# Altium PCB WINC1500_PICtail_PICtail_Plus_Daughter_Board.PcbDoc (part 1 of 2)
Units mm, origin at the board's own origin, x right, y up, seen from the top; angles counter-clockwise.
Board outline 40 x 55.01 mm, 2 copper layers (Top Layer, Bottom Layer), stack 1.571 mm thick; 57 components, 48 nets, 242 pads, 214 vias.
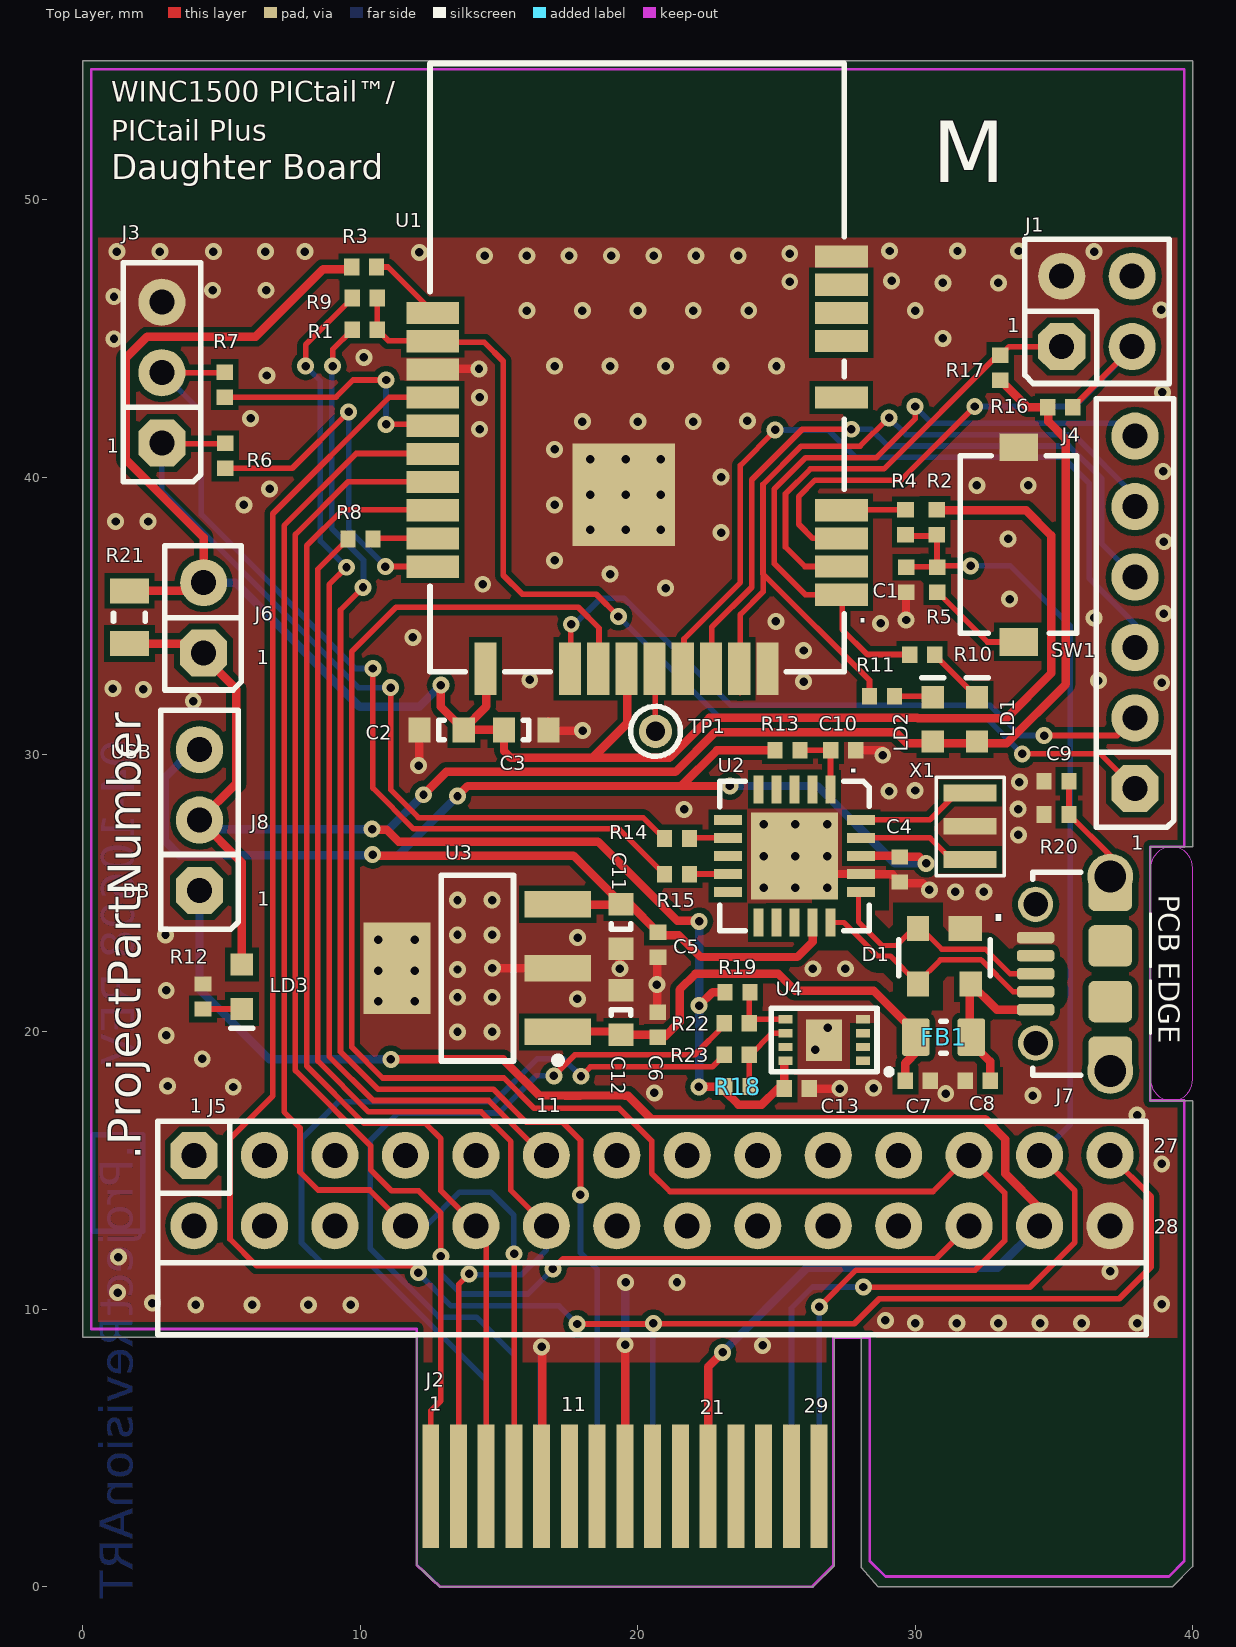
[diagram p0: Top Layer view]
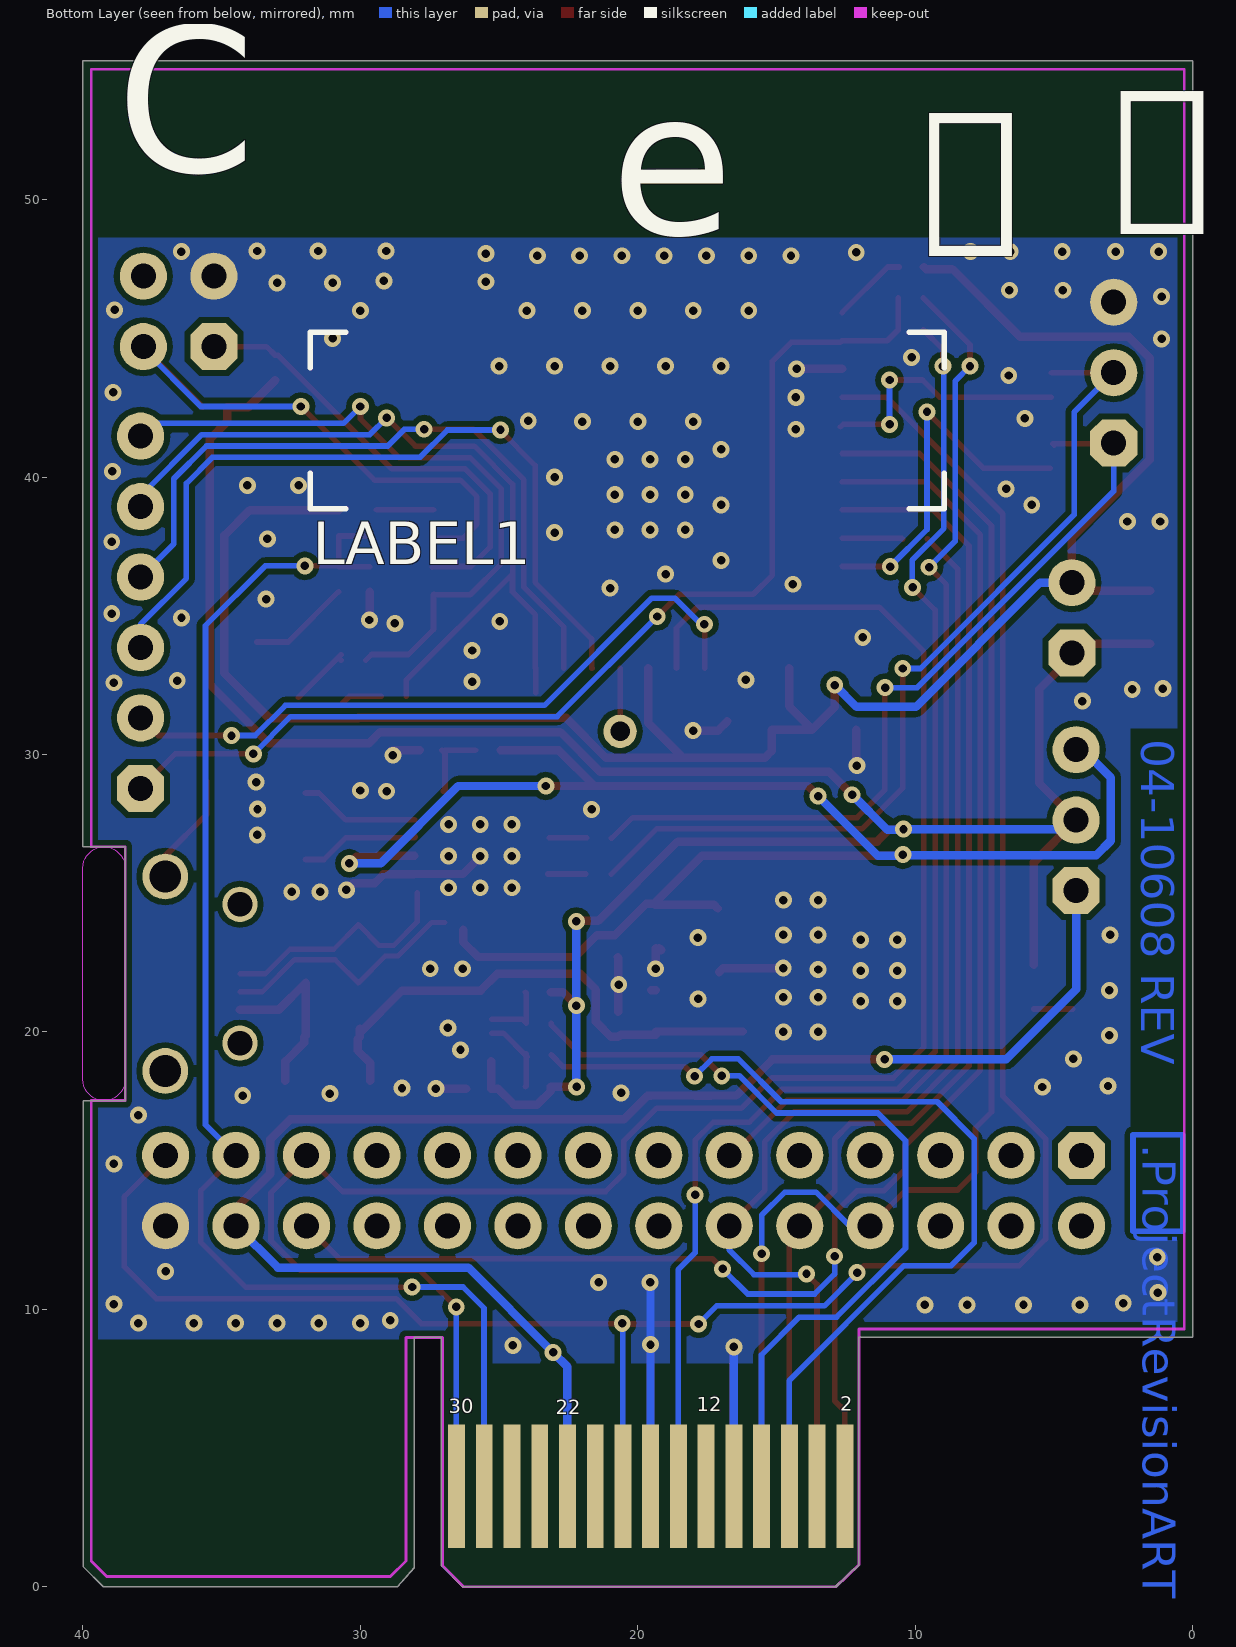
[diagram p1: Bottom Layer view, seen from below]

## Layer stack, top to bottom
Top Solder: solder mask 0.0102, Solder Resist, Dk 3.5
Top Layer: signal copper 0.0356
Dielectric1: core 1.5, FR-4, Dk 4.6
Bottom Layer: signal copper 0.0356
Bottom Solder: solder mask 0.0102, Solder Resist, Dk 3.5

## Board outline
12.862,0 26.317,0 26.317,-0.01 27.078,0.751 27.078,8.989 28.06,8.989 28.06,0.683 28.662,0 39.271,0 39.997,0.726 39.997,17.526 38.475,17.526 38.475,26.675 40,26.675 40,55 0,55 0,8.989 12.029,8.989 12.029,0.79

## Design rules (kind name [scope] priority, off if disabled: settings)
Clearance Clearance_U4 [(InComponent('U4') AND IsPad)] p1: gap=0.2
Clearance "Polygon - USB trace" [InPolygon vs (InNet('USB_P') OR InNet('USB_N'))] p2: gap=0.508
Clearance Clearance_usb [(InNet('USB_N') OR InNet('USB_P'))] p3: gap=0.178
Clearance GND_Via [(IsVia AND InNet('GND')) vs (OnLayer('Keep-Out Layer'))] p4: gap=0.127
Clearance J2 [InComponent('J2') vs (OnLayer('Keep-Out Layer'))] p5: gap=0.1
Clearance [All] p6: gap=0.203
ComponentClearance [All] p1: gap=0.2 collisioncheckmode=3 verticalgap=0.2 showdistances=FALSE
DiffPairsRouting [All] p1: maxlimit=0.191 minlimit=0.191 mostfreqgap=0.191 toplayer_minwidth=0.191 toplayer_maxwidth=0.191 toplayer_prefwidth=0.191 bottomlayer_minwidth=0.191 bottomlayer_maxwidth=0.191 bottomlayer_prefwidth=0.191 maxuncoupledlength=12.7
FabricationTestPointUsage TestPointUsage [All] p1: valid=0 allowmultiple=FALSE
FabricationTestpoint Testpoint [All] p1: side=3 testpointundercomponent=TRUE minsize=1.016 maxsize=2.54 preferedsize=1.524 minholesize=0 maxholesize=1.016 preferedholesize=0.813 testpointgrid=0.025 allowsidetop=TRUE allowsidebottom=TRUE usegrid=TRUE gridtolerance=0
HoleSize [All] p1: absolutevalues=TRUE maxlimit=5 minlimit=0.3 maxpercent=80.000 minpercent=20.000
HoleToHoleClearance [All] p1: gap=0.3 allowstackedmicrovias=TRUE
MinimumSolderMaskSliver MinimumSolderMaskSliver_U2_14_18 [(InComponent('U2') AND IsPad)] p1: minsoldermaskwidth=0.099
MinimumSolderMaskSliver MinimumSolderMaskSliver_U1 [(InComponent('U1') AND IsPad)] p2: minsoldermaskwidth=0.015
MinimumSolderMaskSliver MinimumSolderMaskSliver_U4 [(InComponent('U4') AND IsPad)] p3: minsoldermaskwidth=0.046
MinimumSolderMaskSliver MinimumSolderMaskSliver_J7 [(InComponent('J7') AND IsPad)] p4: minsoldermaskwidth=0.089
MinimumSolderMaskSliver [All] p5: minsoldermaskwidth=0.1
PlaneClearance [All] p1: clearance=0.5
PlaneConnect PlaneConnect_full [IsVia] p1: planeconnectstyle=Direct reliefexpansion=0.5 reliefentries=4 reliefconductorwidth=0.3 reliefairgap=0.3
PlaneConnect [All] p2: planeconnectstyle=Direct reliefexpansion=0.3 reliefentries=4 reliefconductorwidth=0.25 reliefairgap=0.25
PolygonConnect [All] p1: connectstyle=Direct reliefconductorwidth=0.3 reliefentries=4 polygonreliefangle="90 Angle" airgapwidth=0.25
RoutingVias [All] p1: holewidth=0.305 width=0.61 viastyle="Through Hole" minholewidth=0.305 minwidth=0.61 maxholewidth=1.6 maxwidth=2.5
ShortCircuit [IsNet] p1: allowed=FALSE
SilkToSilkClearance [All] p1: silktosilkclearance=0.1
SilkToSolderMaskClearance SilkscreenOverComponentPads [IsPad] p1: minsilkscreentomaskgap=0.1 clearancetoexposedcopper=TRUE
SolderMaskExpansion SolderMaskExpansionTenting [IsVia] p1: expansion=-0.3
SolderMaskExpansion [All] p2: expansion=0.1
Width Width_Vcc_GND [(InNet('VCC_USB_5V0') OR InNet('VCC_USB_3V3') OR InNet('VCC_TARGET_3V3') OR InNet('VCC_MODULE_3V3') OR InNet('VCC_BASE_BOARD_3V3')OR InNet('GND')OR InNet('NetC8_2'))] p1: maxlimit=0.305 minlimit=0.305 preferedwidth=0.305
Width [All] p2: maxlimit=0.203 minlimit=0.2 preferedwidth=0.203
17 further rules are at their usual default settings.

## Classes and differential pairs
differential pair USB: +USB_P -USB_N

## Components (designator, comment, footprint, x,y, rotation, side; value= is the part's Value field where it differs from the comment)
C1 "Capacitor NP" CAP_C_0402 29.675,36.3 r90 top
C2 "Capacitor NP" CAP_C_0603 12.929,30.886 r0 top
C3 "Capacitor NP" CAP_C_0603 15.977,30.886 r180 top
C4 "Capacitor NP" CAP_C_0402 29.439,25.857 r90 top
C5 "Capacitor NP" CAP_C_0402 20.726,23.139 r90 top
C6 "Capacitor NP" CAP_C_0402 20.716,20.259 r90 top
C7 "Capacitor NP" CAP_C_0402 30.092,18.237 r0 top
C8 "Capacitor NP" CAP_C_0402 32.251,18.237 r0 top
C9 "Capacitor NP" CAP_C_0402 35.096,29.032 r0 top
C10 "Capacitor NP" CAP_C_0402 27.407,30.15 r180 top
C11 "Capacitor NP" CAP_C_0603 19.4,23.8 r90 top
C12 "Capacitor NP" CAP_C_0603 19.4,20.7 r270 top
C13 "Capacitor NP" CAP_C_0402 25.73,17.958 r180 top
D1 "PRTR5V0U2X" SOT-143 31.05,22.725 r180 top
FB1 "Ferrite Bead" IND_C_0805 31.023,19.812 r180 top
J1 "Header 2x2" HDR_M_2.54_2x2 36.551,45.974 r0 top locked
J2 "PICtail plus connector" CON_EDGE-CARD_PCB_RA_PICTAIL_PLUS_30A_Alternate1 12.535,0 r0 top locked
J3 "Header 1x3" HDR_M_2.54_1x3 2.845,43.764 r90 top locked
J4 "Header 1x6" HDR_M_2.54_1x6 37.922,35.128 r90 top locked
J5 "Header 2x14" HDR_M_2.54_2x14_RA 4.003,15.55 r0 top locked
J6 "Header 1x2" HDR_M_2.54_1x2 4.35,34.925 r90 top locked
J7 "CON USB2.0 Mini_Micro" CON_USB_Micro-AB_SMD_TH_RA_FCI_10118194-0001LF 37.033,22.098 r270 top locked
J8 "Header 1x3" HDR_M_2.54_1x3 4.2,27.635 r90 top locked
LABEL1 "LABEL_08-00028" LABEL_08-00028 20.376,42.04 r0 bottom
LD1 "LED" LED_0603_RED 32.233,31.264 r90 top
LD2 "LED" LED_0603_Orange 30.632,31.264 r90 top
LD3 "LED" LED_0603_GREEN 5.725,21.625 r270 top
R1 "Resistor" RES_C_0402 10.16,45.314 r0 top
R2 "Resistor" RES_C_0402 30.775,38.375 r90 top
R3 "Resistor" RES_C_0402 10.135,47.574 r180 top
R4 "Resistor" RES_C_0402 29.65,38.375 r270 top
R5 "Resistor" RES_C_0402 30.8,36.3 r90 top
R6 "Resistor" RES_C_0402 5.131,40.767 r270 top
R7 "Resistor" RES_C_0402 5.105,43.332 r270 top
R8 "Resistor" RES_C_0402 10.008,37.77 r0 top
R9 "Resistor" RES_C_0402 10.16,46.457 r180 top
R10 "Resistor" RES_C_0402 30.251,33.601 r0 top
R11 "Resistor" RES_C_0402 28.8,32.1 r0 top
R12 "Resistor" RES_C_0402 4.325,21.275 r270 top
R13 "Resistor" RES_C_0402 25.4,30.15 r180 top
R14 "Resistor" RES_C_0402 21.412,26.975 r0 top
R15 "Resistor" RES_C_0402 21.412,25.679 r0 top
R16 "Resistor" RES_C_0402 35.23,42.52 r180 top
R17 "Resistor" RES_C_0402 33.071,43.942 r270 top
R18 "Resistor" RES_C_0402 23.596,18.032 r180 top
R19 "Resistor" RES_C_0402 23.596,21.436 r180 top
R20 "Resistor" RES_C_0402 35.096,27.838 r0 top
R21 "Resistor" RES_C_0805 1.675,34.95 r270 top
R22 "Resistor" RES_C_0402 23.571,20.318 r180 top
R23 "Resistor" RES_C_0402 23.571,19.175 r180 top
SW1 "Switch 2 Pin" SW_TACT_SMD_CK_KSR231GLFS 33.731,37.567 r180 top
TP1 "Test Point No BOM" TP_1.2x0.7 20.637,30.836 r0 top
U1 "MODULE ATWINC1510-MR210PB" MOD_ATWINC1500-MR210PB 19.975,43.95 r0 top locked
U2 "MCP2200 QFN-20" QFN-20_5X5 25.649,26.343 r270 top
U3 "MCP182XS SOT-223-3_DDPAK-3_TO-220-3" SOT-223-3 14.22,22.301 r90 top
U4 "ATECC508A UDFN-8" UDFN-8_2X3_EP1.5X1.3 26.719,19.706 r180 top
X1 "CSTCE12M0G15L99-R0" RESONATOR_CSTCE-G_L3.2W1.3H0.8 31.979,27.413 r90 top

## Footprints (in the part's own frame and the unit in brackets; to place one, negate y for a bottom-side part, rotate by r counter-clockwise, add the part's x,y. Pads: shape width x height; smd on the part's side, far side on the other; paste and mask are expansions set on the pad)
CAP_C_0402 [mm] "Chip Capacitor, 2-Leads, Body 1.0x0.5mm, IPC High Density"
  rect 0.55x0.6 smd: 1(-0.45,0) 2(0.45,0)
  body extent -0.5,-0.3 0.5,0.3, height 0.2
CAP_C_0603 [mm] "Chip Capacitor, 2-Leads, Body 1.6x0.8mm, IPC Medium Density"
  rect 0.8x0.9 smd: 1(-0.8,0) 2(0.8,0)
  silkscreen extent -0.1,-0.35 0.1,0.35, body extent -0.8,-0.4 0.8,0.4, height 0.3
CON_EDGE-CARD_PCB_RA_PICTAIL_PLUS_30A_Alternate1 [mm] "Mini Edge Mating Card for Samtec MEC1-160-2-X-D"
  rect 0.61x4.45 smd paste-1: 1(0,3.615) 3(1,3.615) 5(2,3.615) 7(3,3.615) 9(4,3.615) 11(5,3.615) 13(6,3.615) 15(7,3.615) 17(8,3.615) 19(9,3.615) 21(10,3.615) 23(11,3.615) 25(12,3.615) 27(13,3.615) 29(14,3.615)
  rect 0.61x4.45 smd far side paste-1: 2(0,3.615) 4(1,3.615) 6(2,3.615) 8(3,3.615) 10(4,3.615) 12(5,3.615) 14(6,3.615) 16(7,3.615) 18(8,3.615) 20(9,3.615) 22(10,3.615) 24(11,3.615) 26(12,3.615) 28(13,3.615) 30(14,3.615)
  body extent -0.1,1.8 0.4,2.3
CON_USB_Micro-AB_SMD_TH_RA_FCI_10118194-0001LF [mil] "FCI USB Micro-AB SMD RA L5W8.8H2.8"
  round 65 hole 45: 0(-138,0) 0(138,0)
  rrect30% 59x62 smd paste-2: 0(-118.5,0) 0(-39.5,0) 0(39.5,0) 0(118.5,0)
  round 50 hole 35: 0(-98.5,-106)
  rrect100% 50x50 hole 35: 0(98.5,-106)
  rrect50% 16x53 smd paste-1.8 mask+3: 1(51.18,-106) 2(25.59,-106) 3(0,-106) 4(-25.59,-106) 5(-51.18,-106)
  Keep-Out Layer board cut-out: 150,57 161.48,59.28 171.21,65.79 177.72,75.52 180,87 180,87 177.72,98.48 171.21,108.21 161.48,114.72 150,117 150,117 -150,117 -161.48,114.72 -171.21,108.21 -177.72,98.48 -180,87 -180,87 -177.72,75.52 -171.21,65.79 -161.48,59.28 -150,57 -150,57
  Keep-Out Layer board cut-out: 150,57 161.48,59.28 171.21,65.79 177.72,75.52 180,87 180,87 177.72,98.48 171.21,108.21 161.48,114.72 150,117 150,117 -150,117 -161.48,114.72 -171.21,108.21 -177.72,98.48 -180,87 -180,87 -177.72,75.52 -171.21,65.79 -161.48,59.28 -150,57 -150,57
  silkscreen extent -144,-110 144,57, body extent -158,-114 158,106, height 108
HDR_M_2.54_1x2 [mm] "Header Male Vertical 4 Way 2.54mm Pitch"
  oct 1.7x1.7 hole 0.9: 1(-1.27,0)
  round 1.7 hole 0.9: 2(1.27,0)
  silkscreen extent -2.6,-1.35 2.6,1.4, body extent -2.54,-1.27 2.54,1.27, height 5.94
HDR_M_2.54_1x3 [mm] "Header Male Vertical 4 Way P=2.54mm"
  oct 1.7x1.7 hole 0.9: 1(-2.54,0)
  round 1.7 hole 0.9: 2(0,0) 3(2.54,0)
  silkscreen extent -3.94,-1.4 3.96,1.4, body extent -3.8,-1.26 3.82,1.28, height 5.94
HDR_M_2.54_1x6 [mm] "Header Male Vertical 6 Way 2.54mm Pitch"
  oct 1.7x1.7 hole 0.9: 1(-6.35,0)
  round 1.7 hole 0.9: 2(-3.81,0) 3(-1.27,0) 4(1.27,0) 5(3.81,0) 6(6.35,0)
  silkscreen extent -7.75,-1.4 7.7,1.4, body extent -7.62,-1.27 7.62,1.27, height 8.38
HDR_M_2.54_2x2 [mm] "Header Male Vertical 2x2 Way 2.54mm Pitch"
  oct 1.7x1.7 hole 0.9: 1(-1.27,-1.27)
  round 1.7 hole 0.9: 2(-1.27,1.27) 3(1.27,-1.27) 4(1.27,1.27)
  silkscreen extent -2.6,-2.6 2.6,2.6, body extent -2.54,-2.54 2.54,2.54, height 5.94
HDR_M_2.54_2x14_RA [mm] "Header Male R/A 2x14 Way 2.54mm Pitch"
  oct 1.7x1.7 hole 0.9: 1(0,0)
  round 1.7 hole 0.9: 2(0,-2.54) 3(2.54,0) 4(2.54,-2.54) 5(5.08,0) 6(5.08,-2.54) 7(7.62,0) 8(7.62,-2.54) 9(10.16,0) 10(10.16,-2.54) 11(12.7,0) 12(12.7,-2.54) 13(15.24,0) 14(15.24,-2.54) 15(17.78,0) 16(17.78,-2.54) 17(20.32,0) 18(20.32,-2.54) 19(22.86,0) 20(22.86,-2.54) 21(25.4,0) 22(25.4,-2.54) 23(27.94,0) 24(27.94,-2.54) 25(30.48,0) 26(30.48,-2.54) 27(33.02,0) 28(33.02,-2.54)
  silkscreen extent -1.3,-6.47 34.32,1.23, body extent -1.27,-12.56 34.29,0.32, height 5.04
IND_C_0805 [mm] "Chip Inductor, 2-Leads, Body 2.0x1.3mm, IPC Medium Density"
  rrect20% 1x1.35 smd: 1(-1,0) 2(1,0)
  silkscreen extent -0.1,-0.58 0.1,0.58, body extent -1,-0.6 1,0.6, height 0.95
LABEL_08-00028 [mm] "Small Serial Number Assembly Label"
  silkscreen extent -11.43,-3.17 11.43,3.17, body extent -11.43,-3.17 11.43,3.17, height 0.3
LED_0603_GREEN [mm] "LED chip 0603"
  rect 0.8x0.8 smd: 1(-0.8,0) 2(0.8,0)
  silkscreen extent 1.5,-0.4 1.5,0.4, body extent -0.81,-0.4 0.81,0.4, height 0.6
LED_0603_Orange [mm] "LED chip 0603"
  rect 0.8x0.8 smd: 1(-0.8,0) 2(0.8,0)
  silkscreen extent 1.5,-0.4 1.5,0.4, body extent -0.81,-0.4 0.81,0.4, height 0.6
LED_0603_RED [mm] "LED chip 0603"
  rect 0.8x0.8 smd: 1(-0.8,0) 2(0.8,0)
  silkscreen extent 1.5,-0.4 1.5,0.4, body extent -0.81,-0.4 0.81,0.4, height 0.6
MOD_ATWINC1500-MR210PB [mm]
  rect 1.9x0.8 smd: 1(7.365,-8.19) 2(7.365,-7.174) 3(7.365,-6.158) 4(7.365,-5.142) 5(7.365,-1.078) 6(7.365,0.954) 7(7.365,1.97) 8(7.365,2.986) 9(7.365,4.002) 10(-7.365,1.964) 11(-7.365,0.948) 12(-7.365,-0.068) 13(-7.365,-1.084) 14(-7.365,-2.1) 15(-7.365,-3.116) 16(-7.365,-4.132) 17(-7.365,-5.148) 18(-7.365,-6.164) 19(-7.365,-7.18)
  rect 0.8x1.9 smd: 20(-5.465,-10.86) 21(-2.417,-10.86) 22(-1.401,-10.86) 23(-0.385,-10.86) 24(0.631,-10.86) 25(1.647,-10.86) 26(2.663,-10.86) 27(3.679,-10.86) 28(4.695,-10.86)
  rect 3.7x3.7 smd: 29(-0.485,-4.59)
  silkscreen extent -7.46,-10.96 7.46,10.96, body extent -7.36,-10.86 7.37,10.86, height 2.11
QFN-20_5X5 [mm]
  rect 1x0.35 smd: 1(-2.4,1.3) 2(-2.4,0.65) 3(-2.4,0) 4(-2.4,-0.65) 5(-2.4,-1.3) 11(2.4,-1.3) 12(2.4,-0.65) 13(2.4,0) 14(2.4,0.65) 15(2.4,1.3)
  rect 0.35x1 smd: 6(-1.3,-2.4) 7(-0.65,-2.4) 8(0,-2.4) 9(0.65,-2.4) 10(1.3,-2.4) 16(1.3,2.4) 17(0.65,2.4) 18(0,2.4) 19(-0.65,2.4) 20(-1.3,2.4)
  rect 3.15x3.15 smd paste+0: 21(0,0)
  silkscreen extent -2.7,-2.7 2.7,2.7, body extent -2.51,-2.51 2.51,2.51, height 0.89
RES_C_0402 [mm] "Chip Resistor, 2-Leads, Body 1.0x0.5mm, IPC Medium Density"
  rect 0.55x0.6 smd: 1(-0.45,0) 2(0.45,0)
  body extent -0.5,-0.3 0.5,0.3, height 0.2
RES_C_0805 [mm] "Chip Resistor, 2-Leads, Body 2.0x1.3mm, IPC Medium Density"
  rect 0.9x1.4 smd: 1(-0.95,0) 2(0.95,0)
  silkscreen extent -0.15,-0.58 0.15,0.58, body extent -1,-0.63 1,0.63, height 0.78
RESONATOR_CSTCE-G_L3.2W1.3H0.8 [mm] "Resonator Murata CSTCE G 8-13.99 MHz L=3.2mm W=1.3mm H=0.8mm"
  rect 0.6x1.9 smd: 1(-1.2,0) 2(0,0) 3(1.2,0)
  silkscreen extent -1.78,-1.22 1.78,1.23, body extent -1.6,-0.65 1.6,0.65, height 0.7
SOT-143 [mm] "SOT143, 4-Leads, Body 2.9x2.5mm (max), Pitch 1.90mm, IPC Medium Density"
  rect 1.2x0.9 smd: 1(-0.75,-1)
  rect 0.8x0.9 smd: 2(0.95,-1) 3(0.95,1) 4(-0.95,1)
  silkscreen extent -1.65,-0.6 1.65,0.7, body extent -1.46,-1.21 1.46,1.21, height 1
SOT-223-3 [mm] "SOT223-3, 4-Leads, Body 6.7x7.3mm (max), Pitch 2.30mm, IPC Medium Density"
  rect 0.95x2.4 smd: 1(-2.3,-2.9) 2(0,-2.9) 3(2.3,-2.9)
  rect 3.3x2.4 smd: 2(0,2.9)
  silkscreen extent -3.45,-3.03 3.35,1.3, body extent -3.3,-3.55 3.4,3.65, height 1.85
SW_TACT_SMD_CK_KSR231GLFS [mm]
  rect 1.4x1 smd: 1(0,-3.51) 2(0,3.51)
  silkscreen extent -2.1,-3.2 2.1,3.2, body extent -1.91,-3.8 1.92,3.81, height 4.5
TP_1.2x0.7 [mm] "Test Point round, diam=1.2mm, drill=0.7mm"
  round 1.2 hole 0.7: 1(0,0)
  silkscreen extent -0.9,-0.9 0.9,0.9
UDFN-8_2X3_EP1.5X1.3 [mm] "PQFN, 8-Leads, Body 3.00x2.00mm, Pitch 0.50mm, Thermal Pad 1.30x1.50mm, IPC Medium Density"
  rect 0.5x0.3 smd paste-0.046 mask+0.076: 1(-1.398,0.75) 2(-1.398,0.25) 3(-1.398,-0.25) 4(-1.398,-0.75) 5(1.398,-0.75) 6(1.398,-0.25) 7(1.398,0.25) 8(1.398,0.75)
  rect 1.3x1.5 smd paste-0.076: 9(0,0)
  silkscreen extent -2.44,-1.14 1.91,1.24, body extent -1.55,-1.05 1.55,1.05, height 0.64

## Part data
C1 C4 C10 C13: library part CAP0279, "Capacitor"
C2: library part CAP0542, "Capacitor"
C3 C11 C12: library part CAP0602, "Capacitor"
C5 C6: library part CAP1207, "Capacitor"
C7 C8: library part CAP0566, "Capacitor"
C9: library part CAP1479, "Capacitor"
D1: library part DIODE1279
FB1: library part IND1291
J1: library part CON0057
J2: library part CON1387
J3 J8: library part CON0465
J4: library part CON0438
J5: library part CON0174
J6: library part CON1108
J7: library part CON1383, "Connector USB Mini"
LD1: library part DIODE1058
LD2: library part LED0123
LD3: library part LED0113
R1 R4 R6 R7 R8 R9 R14 R15 R22 R23: library part RSMT0730
R2: library part RES1012
R3 R20: library part RES1019
R5: library part RES1385
R10 R11 R12: library part RSMT0731
R13 R16 R17 R18 R19: library part RES1462
R21: library part RSMT0519
SW1: library part SWITCH1023, "Switch"
TP1: library part CON1128, "Test Point"
U1: library part MIC6777
U2: library part MIC6326, "USB 2.0 to UART Protocol Conv with GPIO QFN20"
U3: library part MIC0763, "LDO"
U4: library part IC1305
X1: library part OSC1027, "Resonator"

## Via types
v1: diameter 0.61, hole 0.305, Top Layer to Bottom Layer, 214 vias

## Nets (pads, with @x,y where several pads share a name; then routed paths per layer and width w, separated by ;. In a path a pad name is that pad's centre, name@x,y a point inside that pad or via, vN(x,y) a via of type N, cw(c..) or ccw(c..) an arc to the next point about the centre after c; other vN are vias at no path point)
CHIP_EN: J2.30 J5.23 U1.22 | length 69
  Top Layer w0.203: U1.22@18.603,33.103 18.603,34.558 17.855,35.306 14.381,35.306 14.378,35.309 11.286,35.309 9.688,33.71 9.688,19.452 10.801,18.339 15.171,18.339 16.263,17.247 19.328,17.247 20.5,16.075 20.5,14.908 21.158,14.249 30.642,14.249 J5.23@31.943,15.55 31.943,15.482 33.223,14.202 33.223,12.473 32.165,11.415 27.869,11.415 v1(26.543,10.089)
  Bottom Layer w0.203: J2.30@26.542,3.603 v1(26.543,10.089) v1(26.543,10.089)
ECC_I2C_SCL: J2.6 R23.2 | length 33.3
  Top Layer w0.203: v1(17.953,18.402) 18.291,18.74 22.686,18.74 R23.2@23.121,19.175
  Bottom Layer w0.203: J2.6@14.542,3.603 14.542,7.435 10.402,11.575 8.7,11.575 7.875,12.4 7.875,16.15 9.206,17.481 14.827,17.481 16.373,19.027 17.328,19.027 v1(17.953,18.402)
ECC_I2C_SDA: J2.8 R22.2 | length 30
  Top Layer w0.203: v1(16.972,18.418) 17.73,19.175 22.052,19.175 23.121,20.243 R22.2@23.121,20.318
  Bottom Layer w0.203: J2.8@15.542,3.603 15.542,8.358 14.181,9.719 12.833,9.719 10.35,12.202 10.35,16.075 11.35,17.075 14.996,17.075 16.338,18.418 v1(16.972,18.418)
GND: C1.1 C2.1 C3.1 C4.1 C5.1 C6.2 C7.2 C8.1 C9.1 C10.1 C11.1 C12.1 C13.1 D1.1 J1.2 J2.9 J2.10 J2.15 J2.16 J3.3 J5.28 J7.5 R12.1 R20.1 SW1.1 U1.9 U1.12 U1.28 U1.29 U2.17 U2.21 U3.2 U4.4 U4.9 X1.2 | length 41
  Top Layer w0.305: v1(12.1,29.6) 12.129,29.629 C2.1@12.129,30.886 ; U1.12@12.634,43.898 14.273,43.898 v1(14.275,43.9) ; v1@14.707,22.352 v1(14.757,22.301) 16.921,22.301 U3.2@17.073,22.149 ; v1@16.523,8.496 16.561,8.458 16.561,3.622 J2.9@16.542,3.603 ; v1@16.535,8.509 v1(16.535,8.648) ; C3.1@16.777,31.191 17.107,30.861 v1(18.009,30.861) ; C11.1@19.152,22.949 C11.1@19.228,23.025 ; C12.1@19.355,21.501 C12.1@19.52,21.501 ; v1(19.355,22.276) C11.1@19.355,23.025 ; J2.15@19.542,3.603 v1(19.542,8.728) ; C6.2@20.701,20.719 20.701,21.717 20.706,21.722 20.706,22.669 C5.1@20.726,22.689 ; U2.21@25.648,26.343 26.298,25.693 U2.17@28.049,25.693 28.065,25.677 29.169,25.677 C4.1@29.439,25.407 ; C13.1@26.18,17.958 v1(27.28,17.958) ; C10.1@27.857,30.15 28.829,30.15 v1(28.829,29.972) ; C4.1@29.484,25.362 30.269,25.362 v1(30.508,25.123) ; C1.1@29.667,35.872 29.667,34.856 v1(29.675,34.849)
  Bottom Layer w0.305: v1(16.535,8.648) 16.542,8.655 J2.10@16.542,3.603 ; J2.16@19.542,3.603 v1(19.542,8.728) 19.542,10.957 v1(19.558,10.973)
  other v1: 24.501,8.702 30,9.5 31.5,9.5 33,9.5 34.5,9.5 36,9.5 38,9.5 28.925,9.6 4.064,10.16 6.096,10.16 8.128,10.16 9.652,10.16 38.887,10.185 2.5,10.225 1.25,10.6 21.412,10.973 37.023,11.369 1.275,11.885 38.887,15.24 38,17 34.239,17.704 31.1,17.775 20.6,17.8 28.5,17.975 5.415,18.014 3.05,18.05 4.3,19.025 26.391,19.355 3,19.875 13.5,20 14.75,20 26.848,20.142 10.643,21.107 11.963,21.107 17.823,21.191 13.5,21.25 14.75,21.25 3,21.5 20.686,21.707 10.643,22.212 11.963,22.212 13.5,22.25 26.314,22.276 27.483,22.276 10.643,23.317 11.963,23.317 17.831,23.398 2.975,23.5 13.5,23.5 14.75,23.5 13.5,24.75 14.75,24.75 31.45,25.05 32.475,25.05 24.536,25.197 25.679,25.197 26.822,25.197 24.536,26.34 25.679,26.34 26.822,26.34 33.718,27.099 24.536,27.483 25.679,27.483 26.822,27.483 21.666,28.024 33.708,28.034 29.058,28.677 29.997,28.702 33.757,29.007 3.975,31.925 2.175,32.35 1.075,32.375 38.887,32.588 25.975,32.625 36.601,32.664 16.104,32.69 25.975,33.75 11.89,34.219 28.755,34.729 24.975,34.8 36.449,34.925 38.964,35.077 33.4,35.6 21,36 14.409,36.137 19,36.5 17,37 38.964,37.668 33.35,37.775 23,38 18.288,38.1 19.558,38.1 20.828,38.1 1.175,38.4 2.35,38.4 5.8,39 17,39 18.288,39.37 19.558,39.37 20.828,39.37 6.725,39.575 32.225,39.7 34.075,39.7 23,40 38.938,40.208 18.288,40.64 19.558,40.64 20.828,40.64 17,41 14.3,41.725 18,42 20,42 22,42 23.95,42.025 6.045,42.113 14.3,42.875 38.913,43.053 6.629,43.663 17,44 19,44 21,44 23,44 25,44 10.127,44.313 1.118,44.983 31,45 16,46 18,46 20,46 22,46 24,46 30,46 38.862,46.025 1.118,46.507 4.674,46.736 6.604,46.736 31,47 33,47 25.476,47.041 29.15,47.075 14.478,47.981 16.002,47.981 17.526,47.981 19.05,47.981 20.574,47.981 22.098,47.981 23.622,47.981 25.476,48.057 12.125,48.1 1.225,48.125 2.775,48.125 4.7,48.125 6.575,48.125 8,48.125 36.45,48.125 29.075,48.15 31.525,48.15 33.725,48.15
GPIO_1: J4.2 U1.21 | length 24.6
  Top Layer w0.203: U1.21@17.587,33.103 17.587,34.681 v1(17.602,34.696) ; v1(34.646,30.683) 37.287,30.683 J4.2@37.922,31.318
  Bottom Layer w0.203: v1(17.602,34.696) 17.724,34.696 18.662,35.635 19.503,35.635 23.364,31.773 32.704,31.773 33.793,30.683 v1(34.646,30.683)
GPIO_3: J4.3 U1.25 | length 28.7
  Top Layer w0.203: U1.25@21.651,33.103 21.666,33.118 21.666,34.166 23.699,36.199 23.699,40.424 24.95,41.675 v1(24.95,41.7)
  Bottom Layer w0.203: v1(24.95,41.7) 26.863,41.7 27.847,40.716 35.334,40.716 36.275,39.775 36.275,36.344 37.922,34.696 J4.3@37.922,33.858
GPIO_4: J4.4 U1.26 | length 25.6
  Top Layer w0.203: U1.26@22.667,33.103 22.667,34.592 24.106,36.031 24.106,39.905 25.926,41.725 v1(27.7,41.725)
  Bottom Layer w0.203: v1(27.7,41.725) 28.413,41.725 29.015,41.123 35.549,41.123 36.728,39.943 36.728,37.592 J4.4@37.922,36.398
GPIO_5: J4.5 R11.1 U1.27 | length 29.8
  Top Layer w0.203: U1.27@23.683,32.222 23.683,33.103 23.698,33.118 23.698,35.048 24.519,35.869 24.519,36.506 ; R11.1@28.35,32.1 28.35,32.675 24.519,36.506 ; v1(29.058,42.136) 29.036,42.136 28.015,41.115 25.891,41.115 24.512,39.737 24.512,36.513 24.519,36.506
  Bottom Layer w0.203: v1(29.058,42.136) 29.665,41.529 35.717,41.529 37.922,39.324 J4.5@37.922,38.938
GPIO_6: J4.6 R10.1 U1.1 | length 24.7
  Top Layer w0.203: U1.1@27.34,35.76 26.04,35.76 24.919,36.881 24.919,39.568 26.054,40.704 28.604,40.704 29.997,42.097 v1(29.997,42.545) ; U1.1@27.34,35.77 27.366,35.77 27.366,34.508 28.27,33.604 29.598,33.604 R10.1@29.801,33.401
  Bottom Layer w0.203: v1(29.997,42.545) 30.607,41.935 37.465,41.935 J4.6@37.922,41.478
IRQN: J2.18 J5.27 U1.13 | length 80.3
  Top Layer w0.203: v1(12.093,11.321) 11.847,11.567 6.264,11.567 5.3,12.531 5.3,16.15 6.843,17.693 6.843,38.68 11.045,42.882 U1.13@12.634,42.882 ; v1(17.81,9.472) 20.317,9.472 20.523,9.677 20.721,9.479 27.8,9.479 28.705,10.384 37.355,10.384 38.506,11.535 38.506,14.067 J5.27@37.023,15.55
  Bottom Layer w0.203: v1(12.093,11.321) 12.093,11.3 13.268,10.125 17.157,10.125 v1(17.81,9.472) ; J2.18@20.542,3.603 20.542,9.473 v1(20.561,9.492)
NetC8_2: C8.2 D1.4 FB1.1 J7.1 | length 6.6
  Top Layer w0.305: C8.2@32.701,18.237 32.701,18.937 32.023,19.615 FB1.1@32.023,19.812 31.974,19.861 31.974,21.768 32.943,20.798 J7.1@34.341,20.798
NetC9_2: C9.2 J7.0 R20.2 | length 4.5
  Top Layer w0.203: C9.2@35.546,29.032 R20.2@35.546,27.838 37.033,26.351 J7.0@37.033,25.603 J7.0@37.033,25.108
NetC10_2: C10.2 R13.1 U2.1 | length 2.7
  Top Layer w0.203: R13.1@25.85,30.15 C10.2@26.957,30.15 ; U2.1@27.014,28.677 U2.1@26.948,28.743 26.948,30.04 C10.2@27.058,30.15
NetJ2_14: J2.14 R1.1 | length 50.1
  Top Layer w0.203: v1(9,44) 9,44.604 R1.1@9.71,45.314 ; v1(10.094,36.025) 10.094,36.022 9.281,35.209 9.281,19.284 10.633,17.932 14.792,17.932 15.974,16.75 17.275,16.75 17.932,16.093 v1(17.932,14.122)
  Bottom Layer w0.203: v1(9,44) 8.965,43.965 8.965,38.147 10.11,37.003 10.11,36.04 v1(10.094,36.025) ; v1@17.856,14.148 v1@17.932,14.072 ; v1(17.932,14.122) v1@17.932,14.072 ; v1@17.99,14.014 v1@17.932,14.072 ; J2.14@18.542,3.603 18.542,11.43 17.932,12.04 v1@17.932,14.072
NetJ5_11: J5.11 R9.2 | length 38.2
  Top Layer w0.203: v1(8.025,44) 8.025,44.772 R9.2@9.71,46.457 ; v1(9.5,36.75) 8.875,36.125 8.875,19.116 10.464,17.526 14.624,17.526 16.6,15.55 J5.11@16.703,15.55
  Bottom Layer w0.203: v1(8.025,44) 8.559,43.466 8.559,37.691 v1(9.5,36.75)
NetLD1_2: LD1.2 R10.2 | length 2.2
  Top Layer w0.203: R10.2@30.701,33.395 R10.2@30.701,33.401 ; R10.2@30.701,33.595 LD1.2@32.233,32.064
NetLD2_2: LD2.2 R11.2 | length 1.5
  Top Layer w0.203: R11.2@29.25,32.1 30.397,32.1 LD2.2@30.632,31.864
NetLD3_2: LD3.2 R12.2 | length 1.4
  Top Layer w0.203: R12.2@4.325,20.825 LD3.2@5.725,20.825
NetR3_1: R3.1 U1.10 | length 2.7
  Top Layer w0.203: R3.1@10.585,47.574 10.99,47.574 U1.10@12.634,45.93
NetR4_1: R4.1 U1.4 | length 2.1
  Top Layer w0.203: U1.4@27.366,38.818 R4.1@29.421,38.818
NetR5_1: R5.1 SW1.2 | length 3.7
  Top Layer w0.203: R5.1@30.785,35.872 32.6,34.057 SW1.2@33.731,34.057
NetR8_2: R8.2 U1.18 | length 2.2
  Top Layer w0.203: R8.2@10.458,37.77 10.49,37.802 U1.18@12.634,37.802
NetR14_2: R14.2 U2.7 | length 1.4
  Top Layer w0.203: R14.2@21.837,27 U2.7@23.191,27
NetR15_2: R15.2 U2.9 | length 1.4
  Top Layer w0.203: R15.2@21.876,25.693 U2.9@23.249,25.693
NetR18_1: R18.1 R23.1 U4.6 | length 2.8
  Top Layer w0.203: R23.1@23.996,19.11 R23.1@24.021,19.135 ; R23.1@24.021,19.21 R23.1@24.021,19.175 R23.1@24.021,19.135 ; R18.1@24.046,18.032 24.021,18.058 R23.1@24.021,19.135 ; U4.6@25.269,19.956 24.842,19.956 R23.1@24.021,19.135
NetR19_1: R19.1 R22.1 U4.5 | length 2.4
  Top Layer w0.203: R19.1@24.046,21.436 24.021,21.411 R22.1@24.021,20.318 24.159,20.456 U4.5@25.269,20.456
NetTP1_1: TP1.1 U1.24 | length 2.3
  Top Layer w0.203: TP1.1@20.635,30.836 U1.24@20.635,33.103
NetU2_19: U2.19 X1.1 | length 4.3
  Top Layer w0.203: U2.19@28.016,27.028 U2.19@28.049,27.028 ; U2.19@28.049,26.993 30.532,26.993 31.312,26.213 X1.1@31.979,26.213
NetU2_20: U2.20 X1.3 | length 4.3
  Top Layer w0.203: U2.20@28.049,27.643 30.532,27.643 30.532,27.647 31.498,28.613 X1.3@31.979,28.613
RESET_N: C1.2 J2.28 J5.25 R2.1 R4.2 R5.2 | length 49.9
  Top Layer w0.203: v1(28.133,10.805) 28.148,10.79 34.126,10.79 35.75,12.413 35.75,14.283 J5.25@34.483,15.55 ; C1.2@29.667,36.772 R5.2@30.785,36.772 ; R4.2@29.667,37.879 30.785,37.879 R5.2@30.785,36.772 ; v1(32,36.8) 30.813,36.8 R5.2@30.785,36.772
  Bottom Layer w0.203: J2.28@25.542,3.603 25.542,10.041 26.303,10.803 ; 26.311,10.805 v1(28.133,10.805) v1@28.143,10.805 ; v1(32,36.8) 33.431,36.8 35.585,34.646 35.585,16.652 J5.25@34.483,15.55
SPI_MISO: J2.5 J5.10 U1.17 | length 43
  Top Layer w0.203: U1.17@12.634,38.818 9.354,38.818 8.062,37.526 8.062,18.779 10.136,16.705 12.345,16.705 12.9,16.15 12.9,14.273 J5.10@14.163,13.01 14.542,12.631 J2.5@14.542,3.603
SPI_MOSI: J2.7 J5.8 U1.15 | length 49.1
  Top Layer w0.203: J5.8@11.623,13.01 10.333,14.3 8.475,14.3 7.825,14.95 7.825,16.539 7.249,17.115 7.249,38.249 9.85,40.85 U1.15@12.634,40.85 ; v1(15.54,12.004) 15.54,3.606 J2.7@15.542,3.603
  Bottom Layer w0.203: J5.8@11.623,13.01 12.36,13.01 13.575,14.225 14.7,14.225 15.53,13.395 v1@15.53,12.023
SPI_SCK: J2.3 J5.12 R8.1 | length 42.9
  Top Layer w0.203: R8.1@9.558,37.77 8.468,36.681 8.468,18.947 10.296,17.12 14.355,17.12 15.425,16.05 15.425,14.288 J5.12@16.703,13.01 ; J2.3@13.542,3.603 13.542,10.9 v1(13.919,11.278)
  Bottom Layer w0.203: v1(13.919,11.278) 13.947,11.25 15.817,11.25 16.703,12.136 J5.12@16.703,13.01
SPI_SSN: J2.1 J5.24 U1.16 | length 64
  Top Layer w0.203: J2.1@12.542,3.603 12.542,6.342 12.903,6.703 v1(12.903,11.913) 12.903,13.472 12.1,14.275 11.125,14.275 10.375,15.025 10.375,15.891 7.656,18.611 7.656,37.931 9.555,39.83 12.63,39.83 U1.16@12.634,39.834 ; v1(16.942,11.455) 17.308,11.821 30.754,11.821 J5.24@31.943,13.01
  Bottom Layer w0.203: v1(12.903,11.913) 12.903,11.272 13.625,10.55 16.036,10.55 v1(16.942,11.455)
UART_RXD: R6.2 U1.19 | length 13.1
  Top Layer w0.203: R6.2@5.131,40.317 7.542,40.317 v1(9.575,42.35) ; v1(10.9,36.775) 12.623,36.775 U1.19@12.634,36.786
  Bottom Layer w0.203: v1(9.575,42.35) 9.575,38.112 10.9,36.787 v1(10.9,36.775)
UART_TXD: R7.2 U1.14 | length 9.5
  Top Layer w0.203: R7.2@5.105,42.882 9.12,42.882 9.738,43.5 v1(10.925,43.5) ; v1(10.925,41.9) 12.6,41.9 U1.14@12.692,41.808
  Bottom Layer w0.203: v1(10.925,41.9) v1(10.925,43.5)
USB_N: D1.3 J7.2 U2.15 | length 9.1
  Top Layer w0.191: U2.15@26.948,23.943 27.436,23.943 28.642,22.737 29.104,22.737 30.074,21.768 30.905,22.599 32.361,22.599 32.369,22.591 32.387,22.591 33.53,21.448 J7.2@34.341,21.448
USB_P: D1.2 J7.3 U2.16 | length 8.8
  Top Layer w0.191: U2.16@27.953,25.024 27.953,23.965 28.8,23.118 ; 28.798,23.118 28.8,23.118 ; J7.3@34.341,22.098 33.418,22.098 32.536,22.98 30.961,22.98 30.074,23.868 29.324,23.118 28.8,23.118
USB_UART_RXD: J3.1 R6.1 R14.1 | length 29.5
  Top Layer w0.203: J3.1@2.845,41.224 2.87,41.199 5.036,41.199 R6.1@4.985,41.147 ; v1(11.087,32.41) 11.097,32.4 11.097,28.725 12.095,27.727 20.191,27.727 20.943,26.975 R14.1@20.962,26.975
  Bottom Layer w0.203: J3.1@2.845,41.224 2.845,39.494 9.928,32.41 v1(11.087,32.41)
